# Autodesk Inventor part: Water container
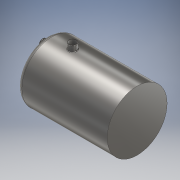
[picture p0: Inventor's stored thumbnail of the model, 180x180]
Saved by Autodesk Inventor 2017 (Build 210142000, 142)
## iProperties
Created: 2020-03
Part Number: Water container
Material: Stainless Steel, 440C
Document SubType Name: Modeling
Designer: user
Density: 7.75 g/cm^3
Appearance: Semi-Polished
Author: user
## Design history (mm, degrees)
sketch "Sketch1"
  geometry: L1 (0, 0)-(285, 0); L2 (300, -15)-(300, -100); L3 (0, -100)-(0, 0); L4 (298, -100)-(298, -15); L5 (285, -2)-(2, -2); L6 (2, -2)-(2, -100); L7 (300, -100)-(298, -100); L8 (2, -100)-(0, -100); A1 r 15 centre (285, -15) between (300, -15) and (285, 0); A2 r 13 centre (285, -15) between (298, -15) and (285, -2); 1 further point
  constraints: 16 end point, 4 perpendicular, 4 point on circle, 3 horizontal, 2 centre point, 2 point on line, 2 tangent, 1 other
  dimensions: "d0" = 300 distance of L1.start point (300, 0); "d1" = 100 distance of point (300, 0) L2.end; "d2" = 15 radius of A1; "d3" = 2 distance between parallel lines of L2 L4
revolve "Revolution1" sketch "Sketch1" stored, may be unused: angle "d4" = 90 deg
sketch "Sketch2"
  geometry: 2 further points
  dimensions: "d5" = 170 distance of point (100, 0) point (-70, 0)
hole "Hole1" sketch "Sketch2" at (-70, 0) diameter "d6" = 6; stored, may be unused: countersink angle "d10" = 90 deg, drill point angle "d12" = 118 deg; dims "d7" = 6, "d8" = 4, "d9" = 2, "d11" = 8
thread "Thread1" dims "d13" = 10, "d14" = 0
chamfer "Chamfer1" distance "d15" = 0.2; stored, may be unused: second distance "d16" = 2, angle "d17" = 45 deg
sketch "Sketch3"
  geometry: C1 r 12.7 at (67.747, 0); 1 further point
  constraints: 1 centre point
  dimensions: "d18" = 25.4 diameter of C1
extrude "Extrusion1" join sketch "Sketch3" distance "d19" = 15; taper "d20" = 0 deg
sketch "Sketch5"
  geometry: L1 (315, -44.953)-(315, -19.553) reference; L2 (315, -19.553)-(312, -19.553); L3 (300, -19.553)-(315, -19.553) reference; L4 (312, -19.553)-(313.5, -18.553); L5 (313.5, -18.553)-(315, -19.553); 1 further point
  constraints: 6 end point, 1 point on line
  dimensions: "d22" = 3 distance of L1.end L2.end; "d31" = 1.5 horizontal distance of L2.end L4.end; "d32" = 1 distance from line of L2 L4.end
sketch "Sketch4"
  geometry: L1 (315, -44.953)-(315, -19.553) reference; L2 (315, -32.253)-(308, -32.253); 1 further point
  constraints: 2 end point, 1 horizontal, 1 midpoint
  dimensions: "d21" = 7 distance of L2.start L2.end
coil "Coil1" sketch "Sketch5", "Sketch4" pitch "d23" = 6; turns "d25" = 1.5; dims "d24" = 10, "d26" = 0, angle "d27" = 90 deg, angle "d28" = 90 deg, "d29" = 0, "d30" = 0
sketch "Sketch6"
  geometry: C1 r 11.5 at (0, 0); 1 further point
  constraints: 1 centre point
  dimensions: "d33" = 23 diameter of C1
extrude "Extrusion2" cut sketch "Sketch6" distance "d34" = 20; taper "d35" = 0 deg
sketch "Sketch7"
  geometry: C1 r 12.7 at (-215.33, 0); 1 further point
  constraints: 1 centre point
  dimensions: "d36" = 25.4 diameter of C1
extrude "Extrusion3" join sketch "Sketch7" stored distance "d37" = 20; taper "d38" = 0 deg
sketch "Sketch8"
  geometry: C1 r 12.7 at (-215.33, 0); A1 r 12.7 centre (-215.33, 0) between (-202.63, 0) and (-228.03, 0) reference; 1 further point
  constraints: 1 centre point, 1 coincident
extrude "Extrusion4" join sketch "Sketch8" distance "d39" = 20; taper "d40" = 0 deg
sketch "Sketch9"
  geometry: C1 r 12.7 at (0, 0) reference; C2 r 11.5 at (0, 0); 1 further point
  constraints: 1 centre point, 1 coincident
  dimensions: "d41" = 23 diameter of C2
extrude "Extrusion5" cut sketch "Sketch9" distance "d42" = 30; taper "d43" = 0 deg
sketch "Sketch10"
  geometry: L1 (228.03, 20)-(228.03, 0) reference; L2 (228.03, 16)-(228.03, 18); L3 (228.03, 20)-(202.63, 20) reference; L4 (203.83, 20)-(226.83, 20) reference; L5 (215.33, 20)-(215.33, 26.797); A1 r 1 centre (228.03, 17) between (228.03, 16) and (228.03, 18); 1 further point
  constraints: 4 end point, 3 point on line, 2 point on circle, 1 centre point, 1 collinear, 1 midpoint, 1 vertical
  dimensions: "d44" = 2 diameter of A1; "d45" = 3 distance from line of L3 A1.centre
revolve "Revolution2" sketch "Sketch10" stored, may be unused: angle "d46" = 90 deg
fillet "Fillet1" dims "d47" = 2
body "Solid1"
